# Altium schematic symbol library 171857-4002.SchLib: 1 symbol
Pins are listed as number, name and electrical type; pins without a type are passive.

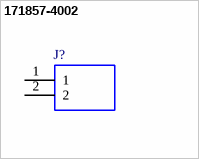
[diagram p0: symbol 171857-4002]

## 171857-4002
designator J?
Headers & Wire Housings KK RPC 254 Hdr FrLk R/A 02 Ckt 15Au T&R; Manufacturer_Name: Molex; Geometry.Height: 6.6mm
footprint 1718574002
pins: 1, 2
